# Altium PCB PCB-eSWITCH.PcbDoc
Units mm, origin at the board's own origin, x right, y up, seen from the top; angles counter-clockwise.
Board outline 50 x 34 mm, 4 copper layers (Top Layer 1, Inner1, Inner2, Bottom Layer 1), stack 1.57 mm thick; 56 components, 38 nets, 225 pads, 153 vias.
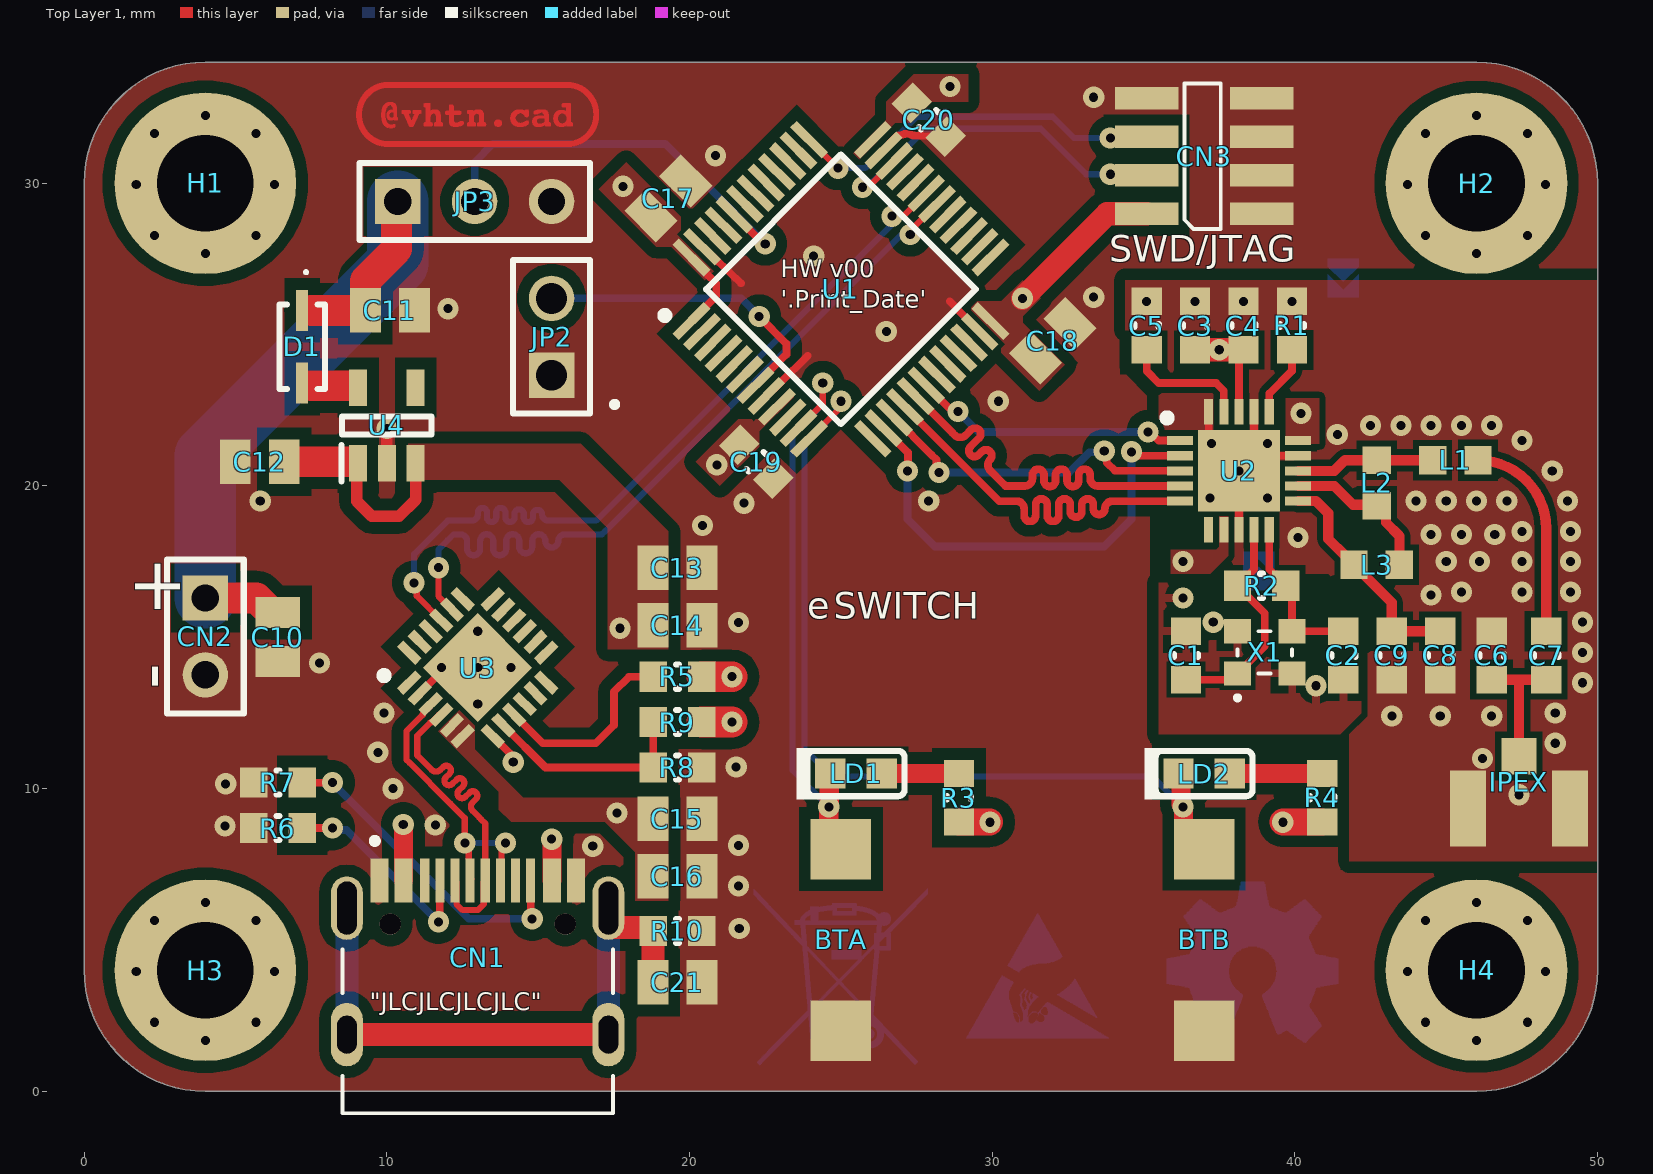
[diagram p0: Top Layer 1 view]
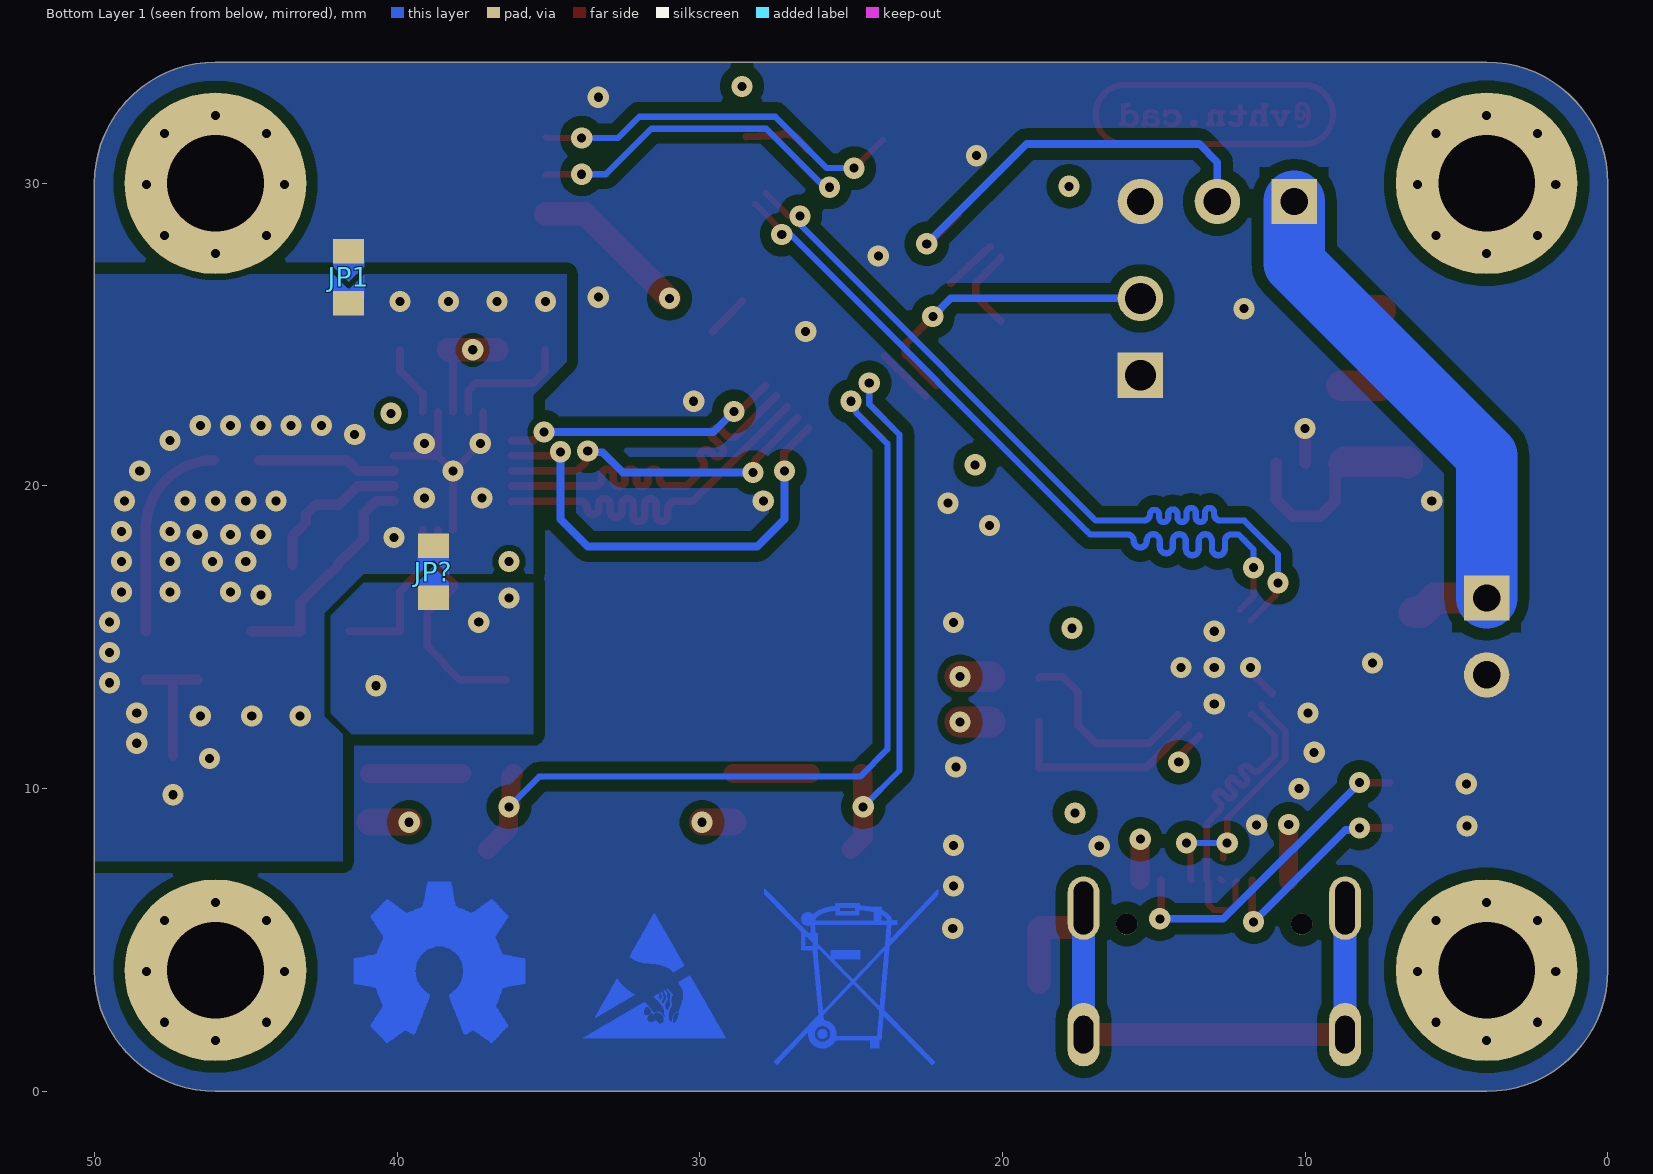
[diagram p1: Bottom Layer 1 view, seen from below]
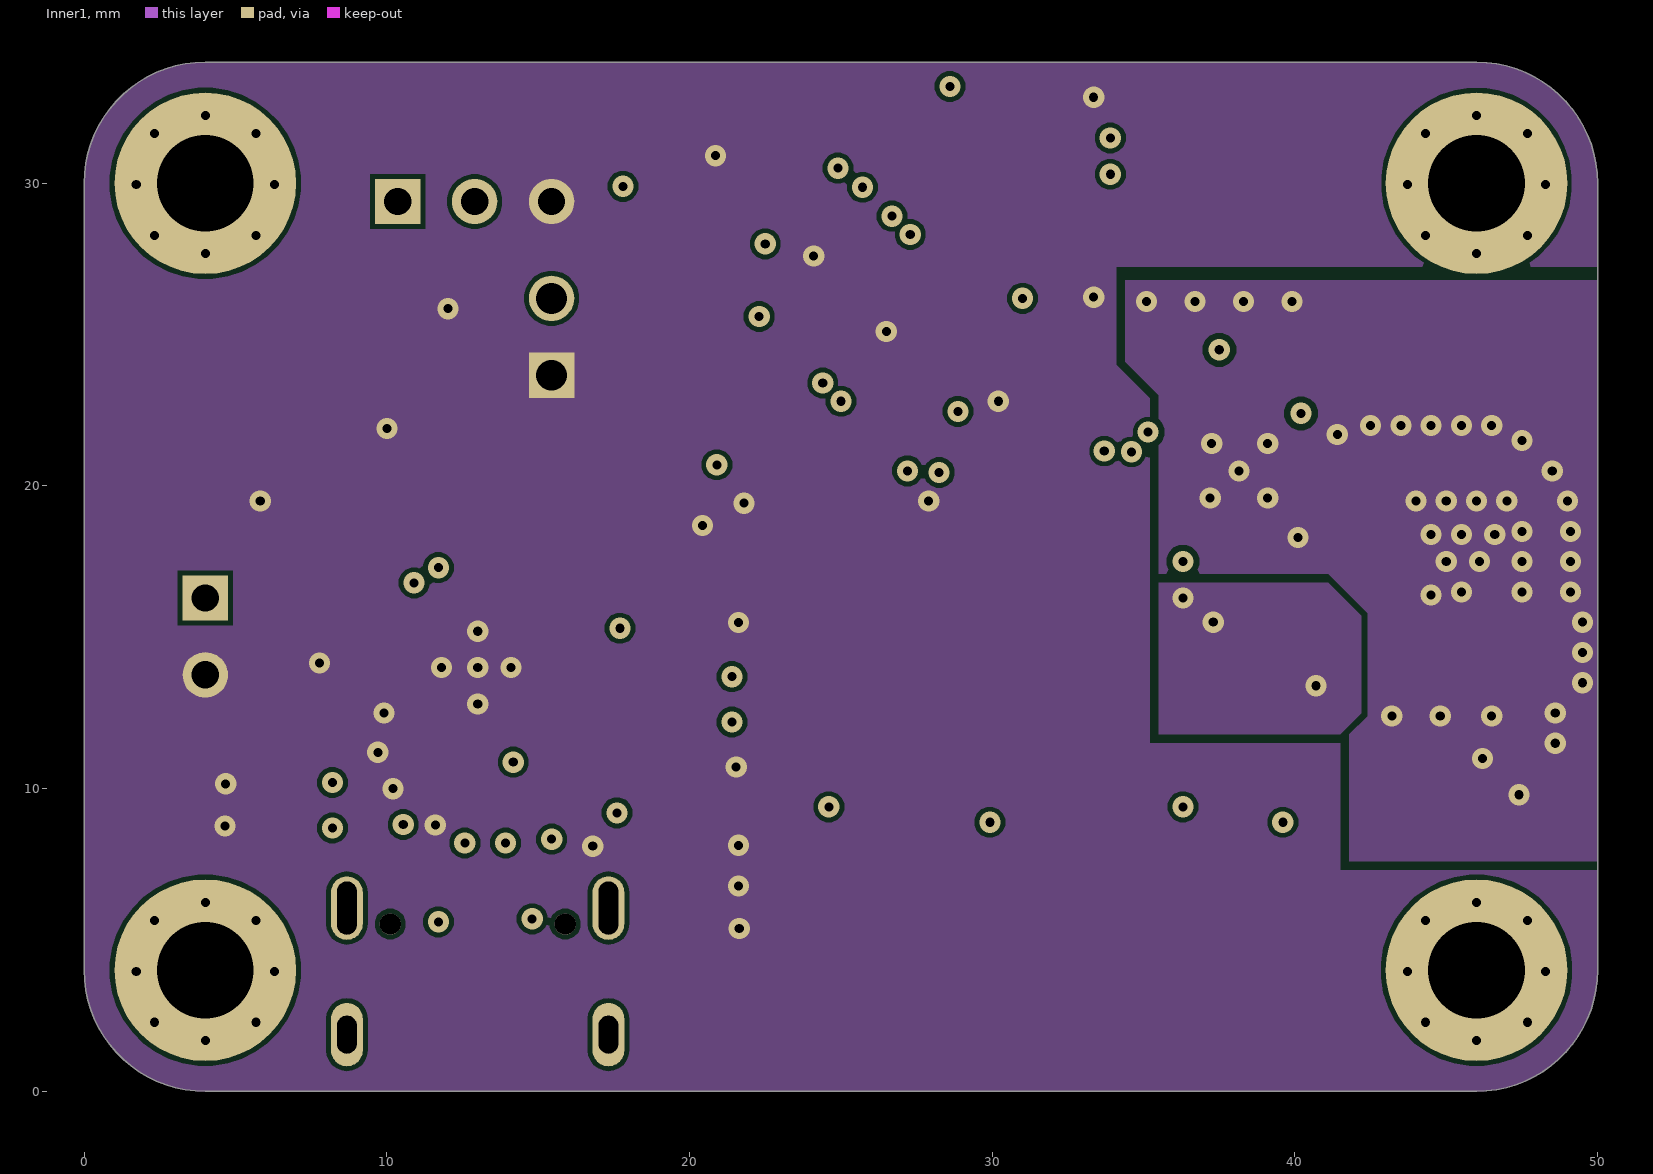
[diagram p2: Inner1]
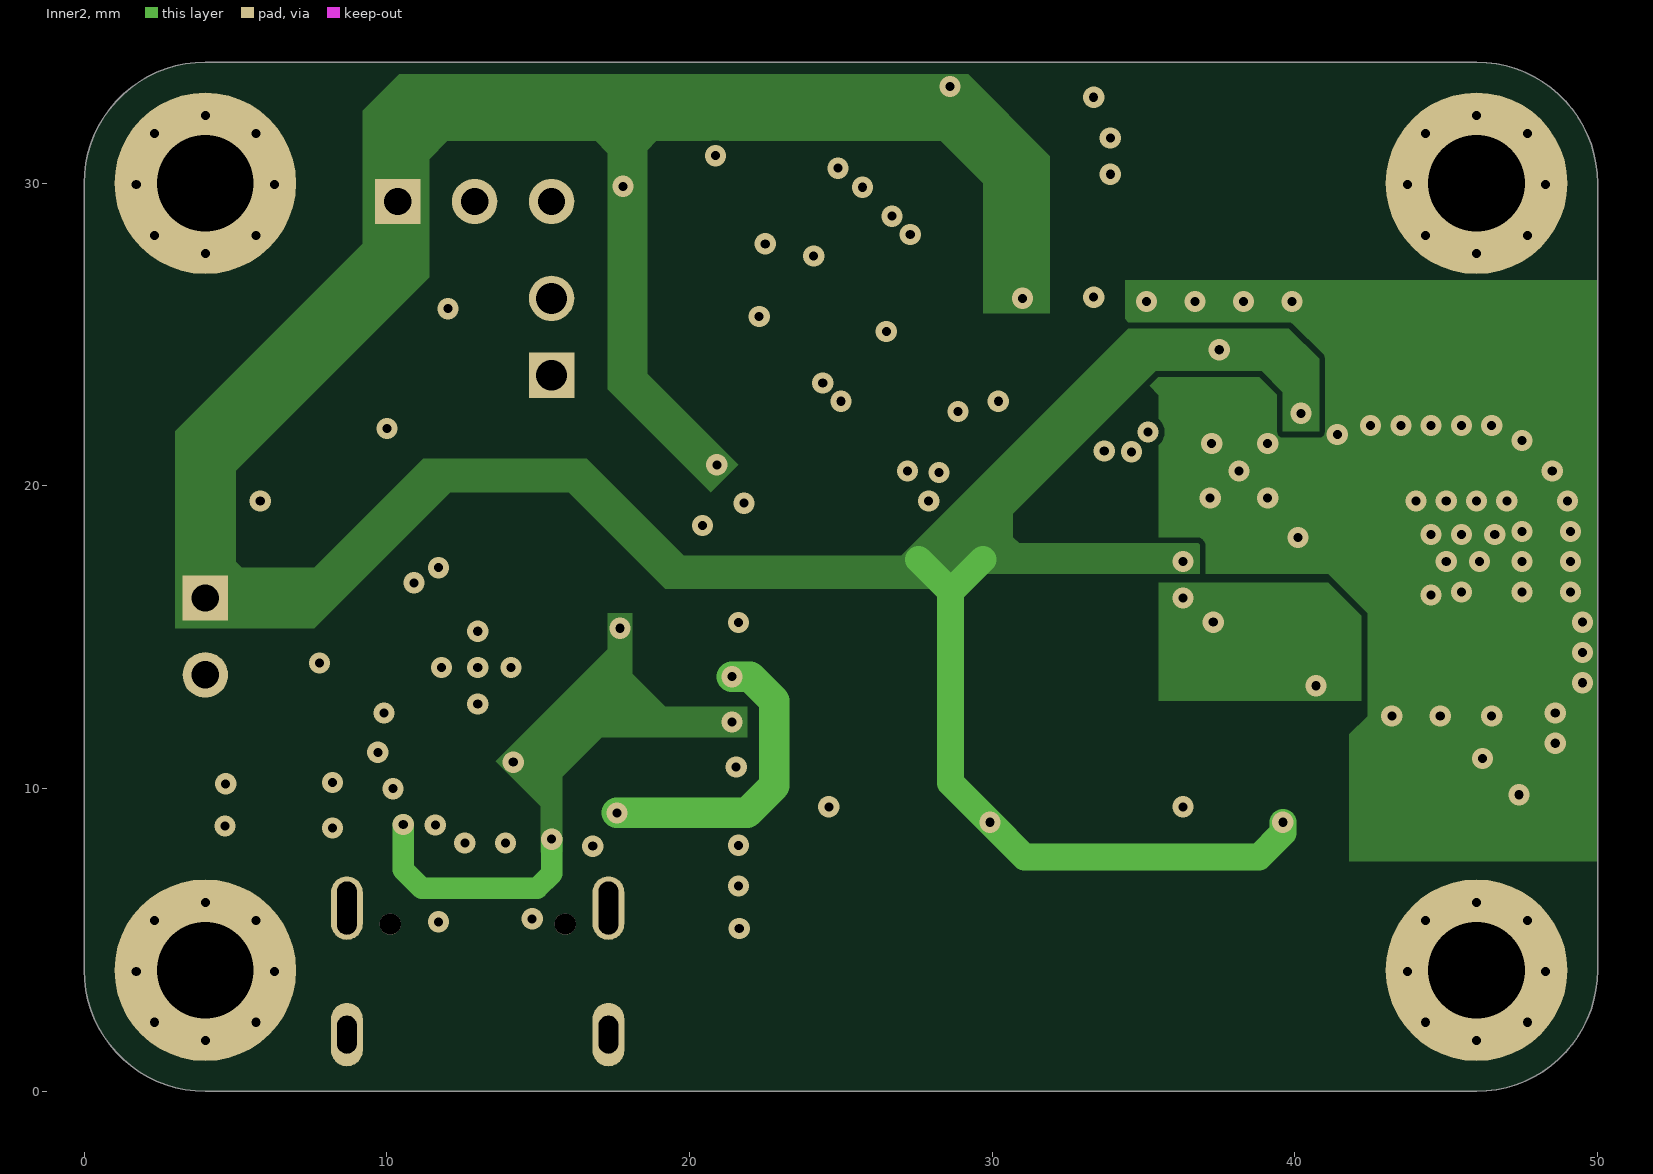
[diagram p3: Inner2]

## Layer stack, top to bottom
Top Solder: solder mask 0.0102, Solder Resist, Dk 3.5
Top Layer 1: signal copper 0.035
Dielectric 2: prepreg 0.2, PP-006, Dk 4.6
Inner1: signal copper 0.0175
Dielectric 1: dielectric 1.065, FR-4, Dk 4.6
Inner2: signal copper 0.0175
Dielectric 3: prepreg 0.2, PP-006, Dk 4.6
Bottom Layer 1: signal copper 0.035
Bottom Solder: solder mask 0.0102, Solder Resist, Dk 3.5

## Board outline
0,4 0,30 cw(c4,30) 4,34 46,34 cw(c46,30) 50,30 50,4 cw(c46,4) 46,0 4,0 cw(c4,4)

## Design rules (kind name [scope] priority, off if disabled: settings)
Clearance Clearance_2 [InNamedPolygon('GND1')] p1: gap=0.152 ignorepadtopadclearanceinfootprint=FALSE
Clearance Clearance_3 [InNamedPolygon('GND')] p2: gap=0.381 ignorepadtopadclearanceinfootprint=FALSE
Clearance Clearance_1 [InNamedPolygon('AGND')] p3: gap=0.203 ignorepadtopadclearanceinfootprint=FALSE
Clearance [All] p4: gap=0.152 ignorepadtopadclearanceinfootprint=FALSE
DiffPairsRouting [All] p1: maxlimit=0.254 minlimit=0.152 mostfreqgap=0.152 toplayer_minwidth=0.152 toplayer_maxwidth=0.381 toplayer_prefwidth=0.229 midlayer1_minwidth=0.152 midlayer1_maxwidth=0.381 midlayer1_prefwidth=0.229 midlayer2_minwidth=0.152 midlayer2_maxwidth=0.381 midlayer2_prefwidth=0.229 bottomlayer_minwidth=0.152 bottomlayer_maxwidth=0.381 bottomlayer_prefwidth=0.229 maxuncoupledlength=12.7
HoleSize [All] p1: absolutevalues=TRUE maxlimit=4 minlimit=0.025 maxpercent=80.000 minpercent=20.000
MinimumSolderMaskSliver [All] p1: minsoldermaskwidth=0.025
PolygonConnect PolygonConnect_6 [All vs IsNamedPolygon('5V')] p1: connectstyle=Direct reliefconductorwidth=0.254 reliefentries=4 polygonreliefangle="90 Angle" airgapwidth=0.254
PolygonConnect PolygonConnect_5 [All vs IsNamedPolygon('3v3P')] p2: connectstyle=Direct reliefconductorwidth=0.254 reliefentries=4 polygonreliefangle="90 Angle" airgapwidth=0.254
PolygonConnect PolygonConnect_4 [All vs IsNamedPolygon('3v3')] p3: connectstyle=Direct reliefconductorwidth=0.254 reliefentries=4 polygonreliefangle="90 Angle" airgapwidth=0.254
PolygonConnect PolygonConnect_3 [All vs IsNamedPolygon('GND1')] p4: connectstyle=Direct reliefconductorwidth=0.254 reliefentries=4 polygonreliefangle="90 Angle" airgapwidth=0.254
PolygonConnect PolygonConnect_2 [All vs IsNamedPolygon('AGND')] p5: connectstyle=Direct reliefconductorwidth=0.254 reliefentries=4 polygonreliefangle="90 Angle" airgapwidth=0.254
PolygonConnect PolygonConnect_1 [All vs IsNamedPolygon('GND')] p6: connectstyle=Direct reliefconductorwidth=0.254 reliefentries=4 polygonreliefangle="90 Angle" airgapwidth=0.254
PolygonConnect PolygonConnect_7 [All vs IsNamedPolygon('XTGND')] p7: connectstyle=Direct reliefconductorwidth=0.254 reliefentries=4 polygonreliefangle="90 Angle" airgapwidth=0.254
PolygonConnect [All] p8: connectstyle=Relief reliefconductorwidth=0.254 reliefentries=4 polygonreliefangle="90 Angle" airgapwidth=0.254
RoutingVias [All] p1: holewidth=0.3 width=0.7 viastyle="Through Hole" minholewidth=0.3 minwidth=0.7 maxholewidth=0.711 maxwidth=1.27
SilkToSilkClearance [All] p1: silktosilkclearance=0
SilkToSolderMaskClearance [IsPad] p1: minsilkscreentomaskgap=0.076 clearancetoexposedcopper=TRUE
SolderMaskExpansion [All] p1: expansion=0.102 istentingtop=FALSE
Width [All] p1: maxlimit=2.54 minlimit=0.152 preferedwidth=0.381
25 further rules are at their usual default settings.

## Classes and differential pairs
differential pair USBD: +USBD_P -USBD_N

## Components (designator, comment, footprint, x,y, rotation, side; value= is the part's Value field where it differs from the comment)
BTA "SWITCH" SKPMAME010 25,5 r90 top
BTB "SWITCH" SKPMAME010 37,5 r90 top
C1 "22pF" 0603C 36.4,14.4 r90 top
C2 "22pF" 0603C 41.6,14.4 r270 top
C3 "10nF" 0603C 36.7,25.3 r90 top
C4 "1nF" 0603C 38.3,25.3 r90 top
C5 "33nF" 0603C 35.1,25.3 r90 top
C6 "1pF" 0603C 46.5,14.4 r90 top
C7 "1.5pF" 0603C 48.3,14.4 r270 top
C8 "4.7pF" 0603C 44.8,14.4 r90 top
C9 "2.2nF" 0603C 43.2,14.4 r90 top
C10 "10uF" CAPC2012X94N 6.4,15.01 r270 top
C11 "1uF" CAPC2012X94N 10.1,25.8 r0 top
C12 "1uF" CAPC2012X94N 5.8,20.8 r180 top
C13 "100nF" CAPC2012X94N 19.6,17.3 r0 top
C14 "4.7uF" CAPC2012X94N 19.6,15.4 r0 top
C15 "100nF" CAPC2012X94N 19.6,9 r0 top
C16 "4.7uF" CAPC2012X94N 19.6,7.1 r0 top
C17 "1uF" CAPC2012X94N 19.3,29.5 r45 top
C18 "1uF" CAPC2012X94N 32,24.8 r45 top
C19 "100nF" 0603C 22.2,20.8 r135 top
C20 "100nF" 0603C 27.9,32.1 r135 top
C21 "100nF" CAPC2012X94N 19.6,3.6 r0 top
CN1 "USB-C" "USB TYPE C" 13,2.975 r0 top locked
CN2 "ER26500" HDR1X2 4,16.3 r270 top
CN3 "JTAG/SWD" "MINI PIN HEADER 2X4" 37,30.9 r90 top
D1 "BAT60JFILM" SOD-323 7.2,24.6 r90 top
H1 "" "MOUNTING HOLE" 4,30 r0 top
H2 "" "MOUNTING HOLE" 46,30 r0 top
H3 "" "MOUNTING HOLE" 4,4 r0 top
H4 "" "MOUNTING HOLE" 46,4 r0 top
IPEX "SMA" IPEX 47.5,9.4 r180 top
JP1 "CLOSED" SB_0603 41.6,26.9 r90 bottom
JP2 "JP2" HDR_1x2_2R54_V_M_S 15.44,23.66 r90 top
JP3 "Header 3" HDR1X3 10.36,29.4 r0 top
JP? "CLOSED" SB_0603 38.8,17.166 r270 bottom
L1 "3.9nH" RESC1608X55N 45.3,20.85 r0 top value=10mH
L2 "8.2nH" RESC1608X55N 42.7,20.1 r90 top value=10mH
L3 "2.7nH" RESC1608X55N 42.7,17.4 r0 top value=10mH
LD1 "Red" 0603D-R 25.5,10.5 r0 top
LD2 "Red" 0603D-R 37,10.5 r0 top
R1 "22K" 0603R 39.9,25.3 r90 top
R2 "1M" 0603R 38.9,16.7 r180 top
R3 "1K" 0603R 28.9,9.7 r270 top
R4 "1K" 0603R 40.9,9.7 r270 top
R5 "1K" 0603R 19.6,13.7 r180 top
R6 "4K7" 0603R 6.4,8.7 r0 top
R7 "4K7" 0603R 6.4,10.2 r0 top
R8 "47K" 0603R 19.6,10.7 r0 top
R9 "22K" 0603R 19.6,12.2 r180 top
R10 "1M" 0603R 19.6,5.3 r180 top
U1 "STM32F103C8T6TR" QFP50P900X900X160-48N 25,26.5 r45 top
U2 "NRF24L01" QFN50P400X400X95-21N-D 38.15,20.5 r0 top
U3 "CP2102N" QFN50P400X400X80-25N-D 13,14 r45 top
U4 "AP2112K-3.3TRG1" SOT95P282X130-5N 10,22 r90 top
X1 "16MHz" XTAL_SMD 39,14.5 r0 top

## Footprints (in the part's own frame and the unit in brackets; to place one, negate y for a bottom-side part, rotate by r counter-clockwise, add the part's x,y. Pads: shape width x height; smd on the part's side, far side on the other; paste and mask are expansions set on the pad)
0603C [mm] "Chip Capacitor, Body 1.6x0.8mm, Height 1.0mm, IPC Medium Density"
  rect 0.9x1 smd: 1(-0.8,0) 2(0.8,0)
  silkscreen extent -0.05,-0.4 0.05,0.4, body extent -0.87,-0.48 0.88,0.47, height 1
0603D-R [mm] "LED, SMT, Body 1.6 x 0.8 mm, 0.25mm Thickness"
  rect 1x1 smd paste+0 mask+0: 1(0.85,0) 2(-0.85,0)
  silkscreen extent -1.98,-0.86 1.6,0.84, body extent -0.8,-0.4 0.8,0.4, height 0.25
0603R [mm] "Chip Resistor, Body 1.6x0.8mm, IPC Medium Density"
  rect 0.9x1 smd: 1(-0.8,0) 2(0.8,0)
  silkscreen extent -0.05,-0.4 0.05,0.4, body extent -0.85,-0.47 0.85,0.47, height 0.6
CAPC2012X94N [mm]
  rect 1.02x1.47 smd: 1(-0.81,0) 2(0.81,0)
  body extent -1,-0.63 1,0.63, height 0.94
HDR1X2 [mm] "Connector; Header; 2 Position"
  rect 1.5x1.5 hole 0.9: 1(0,0)
  round 1.5 hole 0.9: 2(2.54,0)
  silkscreen extent -1.27,-1.27 3.81,1.27
HDR1X3 [mm] "Connector; Header; 3 Position"
  rect 1.5x1.5 hole 0.9: 1(0,0)
  round 1.5 hole 0.9: 2(2.54,0) 3(5.08,0)
  silkscreen extent -1.27,-1.27 6.35,1.27
HDR_1x2_2R54_V_M_S [mm] "Male Header, Pitch 2.54mm, 4x1 Position, Mated Height 6mm, Tail Length 3mm"
  rect 1.5x1.5 hole 1.02: 1(0,0)
  round 1.5 hole 1.02: 2(2.54,0)
  silkscreen extent -1.27,-2.14 3.81,1.27, body extent -1.27,-1.27 3.81,1.27, height 9
IPEX [mm]
  rect 1.2x2.5 smd: 1(-1.585,0.055) 2(1.785,0.055)
  rect 1.15x1.2 smd: 3(0.1,-1.675)
  body extent -1.5,-1.5 1.5,1.6
"MINI PIN HEADER 2X4" [mm]
  rect 0.74x2.1 smd mask+0.01: 1(-1.905,1.9) 2(-1.905,-1.9) 3(-0.635,1.9) 4(-0.635,-1.9) 5(0.635,1.9) 6(0.635,-1.9) 7(1.905,1.9) 8(1.905,-1.9)
  silkscreen extent -2.4,-0.55 2.39,0.65, body extent -2.55,-2.81 2.53,2.76, height 4.4
"MOUNTING HOLE" [mm]
  round 6 hole 3.2 unplated mask+0.05: 1(0,0)
QFN50P400X400X80-25N-D [mm]
  rect 0.85x0.3 smd mask+0.051: 1(-1.95,1.25) 2(-1.95,0.75) 3(-1.95,0.25) 4(-1.95,-0.25) 5(-1.95,-0.75) 6(-1.95,-1.25) 13(1.95,-1.25) 14(1.95,-0.75) 15(1.95,-0.25) 16(1.95,0.25) 17(1.95,0.75) 18(1.95,1.25)
  rect 0.3x0.85 smd mask+0.051: 7(-1.25,-1.95) 8(-0.75,-1.95) 9(-0.25,-1.95) 10(0.25,-1.95) 11(0.75,-1.95) 12(1.25,-1.95) 19(1.25,1.95) 20(0.75,1.95) 21(0.25,1.95) 22(-0.25,1.95) 23(-0.75,1.95) 24(-1.25,1.95)
  rect 2.55x2.55 smd mask+0.051: 25(0,0)
  silkscreen extent -2.5,1.88 -2.25,2.12, body extent -2.05,-2.05 2.05,2.05, height 0.8
QFN50P400X400X95-21N-D [mm]
  rect 0.85x0.3 smd mask+0.05: 1(-1.95,1) 2(-1.95,0.5) 3(-1.95,0) 4(-1.95,-0.5) 5(-1.95,-1) 11(1.95,-1) 12(1.95,-0.5) 13(1.95,0) 14(1.95,0.5) 15(1.95,1)
  rect 0.3x0.85 smd mask+0.05: 6(-1,-1.95) 7(-0.5,-1.95) 8(0,-1.95) 9(0.5,-1.95) 10(1,-1.95) 16(1,1.95) 17(0.5,1.95) 18(0,1.95) 19(-0.5,1.95) 20(-1,1.95)
  rect 2.7x2.7 smd mask+0.05: 21(0,0)
  silkscreen extent -2.5,1.63 -2.25,1.87, body extent -2.05,-2.05 2.05,2.05, height 0.95
QFP50P900X900X160-48N [mm]
  rect 1.475x0.3 smd mask+0.051: 1(-4.238,2.75) 2(-4.238,2.25) 3(-4.238,1.75) 4(-4.238,1.25) 5(-4.238,0.75) 6(-4.238,0.25) 7(-4.238,-0.25) 8(-4.238,-0.75) 9(-4.238,-1.25) 10(-4.238,-1.75) 11(-4.238,-2.25) 12(-4.238,-2.75) 25(4.238,-2.75) 26(4.238,-2.25) 27(4.238,-1.75) 28(4.238,-1.25) 29(4.238,-0.75) 30(4.238,-0.25) 31(4.238,0.25) 32(4.238,0.75) 33(4.238,1.25) 34(4.238,1.75) 35(4.238,2.25) 36(4.238,2.75)
  rect 0.3x1.475 smd mask+0.051: 13(-2.75,-4.238) 14(-2.25,-4.238) 15(-1.75,-4.238) 16(-1.25,-4.238) 17(-0.75,-4.238) 18(-0.25,-4.238) 19(0.25,-4.238) 20(0.75,-4.238) 21(1.25,-4.238) 22(1.75,-4.238) 23(2.25,-4.238) 24(2.75,-4.238) 37(2.75,4.238) 38(2.25,4.238) 39(1.75,4.238) 40(1.25,4.238) 41(0.75,4.238) 42(0.25,4.238) 43(-0.25,4.238) 44(-0.75,4.238) 45(-1.25,4.238) 46(-1.75,4.238) 47(-2.25,4.238) 48(-2.75,4.238)
  silkscreen extent -4.85,-3.15 3.15,3.62, body extent -4.5,-4.5 4.5,4.5, height 1.6
RESC1608X55N [mm]
  rect 0.9x0.95 smd: 1(-0.75,0) 2(0.75,0)
  body extent -0.77,-0.4 0.77,0.4, height 0.55
SB_0603 [mil] "Jumper"
  rect 32x40 smd mask+2: 1(33.75,0) 2(-33.75,0)
  Top Layer 1 region: 23.75,20 13.75,20 -6.25,0 13.75,-20 23.75,-20
  Top Layer 1 region: -26.25,0 -16.25,0 3.75,20 -26.25,20
  Top Layer 1 region: -26.25,0 -16.25,0 3.75,-20 -26.25,-20
SKPMAME010 [mm]
  rect 2x2 smd: 1(-3,0) 2(3,0)
  body extent -3.3,-2.97 3.3,2.97, height 5
SOD-323 [mm] "Diode"
  rect 1.35x0.4 smd: 1(-1.2,0) 2(1.2,0)
  silkscreen extent -1.4,-0.75 2.51,0.75, body extent -1.35,-0.72 1.35,0.72, height 1.17
SOT95P282X130-5N [mm]
  rect 1.2x0.6 smd: 1(-1.25,0.95) 2(-1.25,0) 3(-1.25,-0.95) 4(1.25,-0.95) 5(1.25,0.95)
  silkscreen extent -1.85,-1.48 0.3,1.5, body extent -1.41,-1.48 1.41,1.48, height 1.3
"USB TYPE C" [mm]
  rect 0.6x1.45 smd mask+0.05: A1B12(-3.25,3.995) A4B9(-2.45,3.995) B1A12(3.25,3.995) B4A9(2.45,3.995)
  rect 0.3x1.45 smd mask+0.05: A5(-1.25,3.995) A6(-0.25,3.995) A7(0.25,3.995) A8(1.25,3.995) B5(1.75,3.995) B6(0.75,3.995) B7(-0.75,3.995) B8(-1.75,3.995)
  oval 1.05x2.1 hole 0.65 slot 1.75 at 90 deg mask+0.05: S1(-4.32,3.08) S2(4.32,3.08)
  oval 1.05x2.1 hole 0.65 slot 1.25 at 90 deg mask+0.05: S3(-4.32,-1.1) S4(4.32,-1.1)
  round 0.7 hole 0.7 unplated: ""(-2.89,2.55) ""(2.89,2.55)
  silkscreen extent -4.47,-3.7 4.47,5.4, body extent -4.47,-3.75 4.47,4.15, height 3.16
XTAL_SMD [mm]
  rect 0.9x0.8 smd: 1(-0.9,-0.7) 2(0.9,-0.7) 3(0.9,0.7) 4(-0.9,0.7)
  silkscreen extent -0.95,-1.55 0.9,0.7, body extent -1.65,-1.3 1.65,1.3, height 1.1

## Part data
C1 C2 C3 C4 C5 C6 C7 C8 C9 C10 C11 C12 C13 C14 C15 C16 C17 C18 C19 C20 C21: library part CAP, "Capacitor"
CN2: library part "Header 2", "Header, 2-Pin"
CN3: library part "Header 4X2", "Header, 4-Pin, Dual row"
D1: Manuf_1=STM
H1 H2 H3 H4: library part TP
JP1 JP?: library part "Circuit Breaker", "Circuit Breaker"
JP3: "Header, 3-Pin"
L1 L2 L3: library part Inductor, "Inductor"
LD1 LD2: library part LED2, "Typical RED, GREEN, YELLOW, AMBER GaAs LED"
R1 R2 R3 R4 R5 R6 R7 R8 R9 R10: library part RESISTOR
U1: "Integrated Circuit", Manufacturer_Name=STMicroelectronics, Mouser Part Number=511-STM32F103C8T6TR
U2: "Integrated Circuit", Manufacturer_Name="Nordic Semiconductor", Mouser Part Number=949-NRF24L01
U4: "Integrated Circuit", Manufacturer_Name="Diodes Inc.", Mouser Part Number=621-AP2112K-3.3TRG1
X1: library part XTAL_5032, "Crystal Oscillator"

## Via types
v1: diameter 0.7, hole 0.3, Top Layer 1 to Bottom Layer 1, tented both sides, 153 vias

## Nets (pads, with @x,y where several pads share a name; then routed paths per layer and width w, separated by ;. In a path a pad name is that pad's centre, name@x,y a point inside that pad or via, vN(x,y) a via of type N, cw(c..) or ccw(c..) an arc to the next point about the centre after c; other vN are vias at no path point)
3V3: C3.1 C4.1 C10.1 C11.1 C17.1 C18.1 C19.2 C20.2 CN2.1 CN3.1 D1.2 JP3.1 R3.2 R4.2 U1.1 U1.9 U1.24 U1.36 U1.48 U2.7 U2.15 U2.18 | length 60.5
  Top Layer 1 w0.152: D1.2 7.5,25.8
  Top Layer 1 w0.254: U1.1 20.879,26.268 20.879,26.695 20.559,27.015 20.559,27.019 20.059,27.52 U1.48 ; U2.18 38.15,24.35 C4.1
  Top Layer 1 w0.762: v1(31,26.2) 33.795,28.995 CN3.1 ; C3.1 C4.1
  Top Layer 1 w0.889: R3.2 28.906,8.894 v1@29.917,8.894 ; v1@39.609,8.9 R4.2
  Top Layer 1 w1.016: CN2.1 5.695,16.3 6.175,15.82 C10.1 ; 7.5,25.8 C11.1 9.292,25.802 9.292,26.792 10.318,27.818 10.318,29.358 JP3.1
  Inner2 w0.889: 27.559,17.577 28.626,16.51 ; 29.693,17.577 28.626,16.51 ; v1(39.599,8.89) 39.599,8.534 38.811,7.747 31.064,7.747 v1(29.921,8.89) 28.626,10.185 28.626,16.51
  Bottom Layer 1 w2.032: CN2.1 4,21 10.36,27.36 JP3.1
  other v1: 36.3,17.5 20.9,20.7 40.2,22.4 37.5,24.5 17.8,29.9 28.6,33.2
3V3P: C15.1 C16.1 R5.1 U3.5 U3.6 | length 11.1
  Top Layer 1 w1.016: R5.1 v1(21.4,13.7)
  Inner2 w1.016: v1(17.6,9.2) 21.9,9.2 22.8,10.1 22.8,12.9 22,13.7 v1(21.4,13.7)
+5: C12.1 C13.1 C14.1 CN1.A4B9 CN1.B4A9 R9.1 U3.7 U4.1 U4.3 | length 20.7
  Top Layer 1 w0.152: 8.7,20.8 9,20.8 U4.1
  Top Layer 1 w0.254: U3.7 14.089,11.143 14.089,10.96 v1(14.175,10.875)
  Top Layer 1 w0.381: U4.1 9,20.7 9,19.5 9.5,19 10.4,19 10.95,19.55 U4.3
  Top Layer 1 w0.635: v1(10.541,8.814) 10.55,8.805 CN1.A4B9 ; v1(15.443,8.331) 15.45,8.324 CN1.B4A9
  Top Layer 1 w1.016: C12.1@6.612,20.75 6.61,20.752 C12.1 8.7,20.8 ; R9.1 v1(21.4,12.2)
  Inner2 w0.711: v1(10.541,8.814) 10.541,7.315 11.151,6.706 14.961,6.706 15.443,7.188 v1(15.443,8.331)
  other v1: 17.7,15.3
AGND: C3.2 C4.2 C5.2 C6.2 C8.1 C9.1 IPEX.1 IPEX.2 JP1.2 JP?.2 R1.2 U2.8 U2.14 U2.17 U2.20 U2.21 | length 7.9
  Top Layer 1 w0.254: U2.20 37.15,21.5 v1(38.15,20.5) ; U2.8 v1(38.15,20.5) ; U2.17 U2.21@38.65,21 ; U2.14 U2.21@38.65,21 ; v1(38.15,20.5) U2.21@38.65,21
  other v1: 47.4,9.8 46.2,11 48.6,11.5 43.2,12.4 44.8,12.4 46.5,12.4 48.6,12.5 49.5,13.5 49.5,14.5 49.5,15.5 44.5,16.4 45.5,16.5 47.5,16.5 49.1,16.5 45,17.5 46.1,17.5 47.5,17.5 49.1,17.5 40.1,18.3 44.5,18.4 45.5,18.4 46.6,18.4 47.5,18.5 49.1,18.5 44,19.5 45,19.5 46,19.5 47,19.5 49,19.5 37.2,19.6 39.1,19.6 48.5,20.5 37.25,21.4 39.1,21.4 47.5,21.5 41.4,21.7 42.5,22 43.5,22 44.5,22 45.5,22 46.5,22 35.1,26.1 36.7,26.1 38.3,26.1 39.9,26.1
Button_A: BTA.2 LD1.2 U1.11 | length 19.4
  Top Layer 1 w0.203: U1.11 24.4,22.718 v1(24.4,23.4)
  Top Layer 1 w0.635: LD1.2 24.613,10.464 24.613,9.431 24.6,9.418 v1(24.6,9.4) 24.6,8.4 BTA.2
  Bottom Layer 1 w0.203: v1(24.4,23.4) 24.4,22.7 23.4,21.7 23.4,10.6 v1(24.6,9.4)
Button_B: BTB.2 LD2.2 U1.12 | length 29.5
  Top Layer 1 w0.203: U1.12 v1@24.909,22.52
  Top Layer 1 w0.635: LD2.2 36.236,10.413 36.236,9.481 36.3,9.418 v1(36.3,9.4) 36.3,9.382 36.317,9.365 36.317,8.682 BTB.2
  Bottom Layer 1 w0.203: v1(25.004,22.799) 25.004,22.664 24.841,22.502 24.841,22.441 23.8,21.4 23.8,11.3 24.7,10.4 35.3,10.4 v1(36.3,9.4)
CE: U1.18 U2.1 | length 9.1
  Top Layer 1 w0.254: U1.18 28.596,22.55 28.779,22.55 v1(28.865,22.465) ; v1(35.15,21.781) 35.224,21.781 35.505,21.5 U2.1
  Bottom Layer 1 w0.254: v1(28.865,22.465) 29.549,21.781 v1(35.15,21.781)
CSN: U1.14 U2.2 | length 15.1
  Top Layer 1 w0.254: U1.14 27.215,21.103 27.215,20.515 v1(27.2,20.5) ; v1@34.85,21 U2.2
  Bottom Layer 1 w0.254: v1(27.2,20.5) 27.2,18.9 28.1,18 33.7,18 34.6,18.9 v1(34.6,21.129)
GND: BTA.1 BTB.1 C10.2 C11.2 C12.2 C13.2 C14.2 C15.2 C16.2 C17.2 C18.2 C19.1 C20.1 C21.2 CN1.A1B12 CN1.B1A12 CN2.2 CN3.2 CN3.4 CN3.6 CN3.7 CN3.8 JP1.1 JP2.1 JP3.3 R6.1 R7.1 R8.2 R10.1 U1.8 U1.23 U1.35 U1.47 U3.2 U3.25 U4.2 | length 9.7
  Top Layer 1 w0.254: U3.2 11.8,13.861 v1(11.8,14) ; U1.47 20.858,27.488 21.7,26.7 ; U1.8 22.972,23.398 23.9,24.3 ; U1.35 26.798,31.498 26.821,31.521 26.829,31.528 26.836,31.535 cw(c27.001,31.342) 26.953,31.591 27.011,31.602 ccw(c26.964,31.852) 27.063,31.618 cw(c27.175,31.362) 27.307,31.608 ccw(c27.426,31.832) 27.414,31.578 28.027,31.553 C20.1 ; 28.6,26.1 29.158,25.532 29.16,25.53 U1.23
  Top Layer 1 w0.381: U4.2 v1(10,21.9)
  other v1: 21.641,5.385 21.615,6.782 16.8,8.1 21.615,8.128 4.648,8.763 11.6,8.8 10.2,10 4.674,10.16 21.539,10.719 9.7,11.2 9.9,12.5 13,12.8 13,14 14.1,14 7.772,14.148 13,15.2 21.615,15.494 20.422,18.694 21.793,19.431 5.817,19.507 27.9,19.5 30.2,22.8 26.5,25.1 12.014,25.857 33.35,26.238 24.1,27.6 20.853,30.912 33.35,32.842
MISO: U1.16 U2.5 | length 14.1
  Top Layer 1 w0.254: U1.16 30.232,19.5 30.291,19.5 30.799,19.5 cw(c30.799,19.246) 31.053,19.246 31.053,19.02 ccw(c31.243,19.02) 31.434,19.02 31.434,19.385 cw(c31.624,19.385) 31.815,19.385 31.815,19.02 ccw(c32.005,19.02) 32.196,19.02 32.196,19.385 cw(c32.386,19.385) 32.577,19.385 32.577,19.159 ccw(c32.767,19.159) 32.958,19.159 32.958,19.385 cw(c33.148,19.385) 33.339,19.385 33.339,19.246 ccw(c33.529,19.246) 33.72,19.246 cw(c33.974,19.246) 33.974,19.5 34.506,19.5 U2.5
MOSI: U1.17 U2.4 | length 14.1
  Top Layer 1 w0.254: U1.17 28.671,21.769 28.76,21.679 ccw(c28.94,21.858) 29.12,21.679 29.297,21.856 cw(c29.432,21.722) 29.567,21.856 cw(c29.432,21.722) 29.567,21.587 29.278,21.298 ccw(c29.413,21.164) 29.278,21.029 ccw(c29.413,21.164) 29.547,21.029 29.659,21.14 cw(c29.793,21.005) 29.928,21.14 cw(c29.793,21.005) 29.928,20.871 ccw(c30.107,20.691) 29.928,20.511 30.334,20.105 30.424,20.015 30.439,20 30.947,20 31.074,20 ccw(c31.074,20.254) 31.328,20.254 31.328,20.366 cw(c31.519,20.366) 31.709,20.366 31.709,20.172 ccw(c31.9,20.172) 32.09,20.172 32.09,20.366 cw(c32.281,20.366) 32.471,20.366 32.471,20.172 ccw(c32.662,20.172) 32.852,20.172 32.852,20.366 cw(c33.043,20.366) 33.233,20.366 33.233,20.254 ccw(c33.487,20.254) 33.487,20 33.952,20 U2.4
NetC1_1: C1.1 R2.2 U2.9 X1.1 | length 7.6
  Top Layer 1 w0.254: C1.1 37.95,13.6 38.423,14.073 38.423,14.123 39,14.7 39,15.8 38.473,16.327 38.423,16.327 38.1,16.65 R2.2 38.1,16.75 38.423,17.073 38.473,17.073 38.65,17.25 U2.9
NetC2_1: C2.1 R2.1 U2.10 X1.3 | length 5.4
  Top Layer 1 w0.254: U2.10 39.15,17.25 39.327,17.073 39.377,17.073 39.7,16.75 R2.1 39.9,16.5 X1.3 C2.1
NetC5_1: C5.1 U2.19 | length 4.2
  Top Layer 1 w0.254: C5.1 35.1,23.8 35.5,23.4 37.4,23.4 37.65,23.15 U2.19
NetC6_1: C6.1 C7.2 IPEX.3 | length 4.3
  Top Layer 1 w0.337: C6.1@46.6,13.6 47.45,13.6 ; IPEX.3 47.4,13.55 cw(c47.45,13.55) 47.45,13.6 ; C7.2 47.45,13.6
NetC7_1: C7.1 L1.2 | length 6.9
  Top Layer 1 w0.337: L1.2 cw(c46.05,18.6) 48.3,18.6 C7.1
NetC8_2: C8.2 C9.2 L3.1 U2.11 | length 7.6
  Top Layer 1 w0.337: U2.11 40.7,19.5 41.1,19.1 41.1,18.25 41.643,17.707 41.668,17.707 41.95,17.425 L3.1 41.95,17.375 42.232,17.093 42.257,17.093 43.2,16.15 C9.2 ; C9.2 C8.2
NetC21_1: C21.1 CN1.S1 CN1.S2 CN1.S3 CN1.S4 R10.2 | length 20.8
  Top Layer 1 w0.762: CN1.S3 CN1.S4 ; CN1.S2 17.32,5.608 17.509,5.419 18.731,5.419 18.8,5.35 R10.2 18.795,5.295 18.795,3.605 C21.1
  Bottom Layer 1 w0.762: CN1.S3 CN1.S1 ; CN1.S4 CN1.S2
NetCN1_A5: CN1.A5 R6.2 | length 7.2
  Top Layer 1 w0.254: R6.2 v1(8.2,8.7) ; v1(11.7,5.6) 11.75,5.65 CN1.A5
  Bottom Layer 1 w0.254: v1(8.2,8.7) 8.263,8.637 8.663,8.637 v1(11.7,5.6)
NetCN1_B5: CN1.B5 R7.2 | length 10.8
  Top Layer 1 w0.254: R7.2 v1(8.2,10.2) ; CN1.B5 14.751,5.749 v1(14.8,5.7)
  Bottom Layer 1 w0.254: v1(8.2,10.2) 12.7,5.7 v1(14.8,5.7)
NetCN3_3: CN3.3 U1.34 | length 12.2
  Top Layer 1 w0.203: v1(25.715,29.87) 25.896,29.87 U1.34 ; v1(33.9,30.3) 35.065,30.3 CN3.3
  Bottom Layer 1 w0.203: v1(25.715,29.87) 25.849,29.87 26.031,30.052 26.052,30.052 27.8,31.8 31.6,31.8 33.1,30.3 v1(33.9,30.3)
NetCN3_5: CN3.5 U1.37 | length 12.6
  Top Layer 1 w0.203: U1.37 24.889,30.5 v1(24.9,30.5) ; v1(33.9,31.5) 35.065,31.5 CN3.5
  Bottom Layer 1 w0.203: v1(24.9,30.5) 25.8,30.5 27.5,32.2 32,32.2 32.7,31.5 v1(33.9,31.5)
NetD1_1: D1.1 U4.5 | length 1.6
  Top Layer 1 w0.152: D1.1 7.287,23.313 7.508,23.313
  Top Layer 1 w1.016: 7.508,23.313 U4.5@8.8,23.313
NetJP2_2: JP2.2 U1.7 | length 10.2
  Top Layer 1 w0.254: U1.7 23.2,24.346 23.2,24.7 v1(22.3,25.6)
  Bottom Layer 1 w0.254: JP2.2 21.7,26.2 v1(22.3,25.6)
NetJP3_2: JP3.2 U1.44 | length 13.9
  Top Layer 1 w0.254: U1.44 22.439,28 v1(22.5,28)
  Bottom Layer 1 w0.254: JP3.2 12.9,30.7 13.5,31.3 19.2,31.3 v1(22.5,28)
NetL1_1: L1.1 L2.2 U2.13 | length 4.6
  Top Layer 1 w0.337: U2.13 41.3,20.5 41.65,20.85 L2.2 L1.1
NetL2_1: L2.1 L3.2 U2.12 | length 5.1
  Top Layer 1 w0.337: U2.12 41.3,20 41.917,19.383 42.667,19.383 L2.1 42.725,19.35 43.007,19.068 43.007,18.793 43.45,18.35 L3.2
NetLD1_1: LD1.1 R3.1 | length 2.5
  Top Layer 1 w0.635: LD1.1 R3.1
NetLD2_1: LD2.1 R4.1 | length 3
  Top Layer 1 w0.635: LD2.1 R4.1
NetR1_1: R1.1 U2.16 | length 2.4
  Top Layer 1 w0.254: U2.16 39.153,22.453 39.153,23.053 39.9,23.8 R1.1
NetR5_2: R5.2 U3.9 | length 6.6
  Top Layer 1 w0.254: U3.9 15.146,11.5 16.9,11.5 17.5,12.1 17.5,13.2 18,13.7 18.75,13.7 R5.2@18.8,13.65
NetR8_1: R8.1 R9.2 U3.8 | length 7
  Top Layer 1 w0.254: U3.8 15.239,10.7 R8.1 R9.2
SCK: U1.15 U2.3 | length 11.1
  Top Layer 1 w0.254: U1.15 27.991,21.034 27.991,21.031 28.159,20.863 28.159,20.532 v1(28.245,20.447) ; v1(33.7,21.151) 33.785,21.066 33.785,20.772 34.057,20.5 U2.3
  Bottom Layer 1 w0.254: v1(28.245,20.447) 32.547,20.447 33.213,21.113 33.661,21.113 v1(33.7,21.151)
UART_RXD: U1.31 U3.21 | length 27
  Top Layer 1 w0.203: v1(10.9,16.8) 10.987,16.713 10.987,16.367 U3.21 ; v1(26.687,28.913) 26.688,28.914 27.061,28.914 U1.31
  Bottom Layer 1 w0.203: v1(10.9,16.8) 10.9,17.747 12.011,18.857 12.7,18.857 12.802,18.857 ccw(c12.802,19.06) 13.005,19.06 13.005,19.123 cw(c13.156,19.123) 13.308,19.123 13.308,18.962 ccw(c13.46,18.962) 13.611,18.962 13.611,19.123 cw(c13.763,19.123) 13.914,19.123 13.914,18.962 ccw(c14.066,18.962) 14.218,18.962 14.218,19.074 cw(c14.369,19.074) 14.521,19.074 14.521,18.962 ccw(c14.672,18.962) 14.824,18.962 14.824,19.06 cw(c14.976,19.06) 15.127,19.06 ccw(c15.33,19.06) 15.33,18.857 16.2,18.857 16.911,18.857 26.777,28.723 26.777,28.823 v1(26.687,28.913)
UART_TXD: U1.30 U3.20 | length 26.9
  Top Layer 1 w0.203: v1(11.7,17.3) 11.7,16.361 U3.20 ; v1(27.29,28.31) 27.29,28.436 U1.30
  Bottom Layer 1 w0.203: v1(11.7,17.3) 11.7,17.9 12.011,18.211 12.2,18.4 12.436,18.4 cw(c12.436,18.185) 12.651,18.185 12.651,17.925 ccw(c12.866,17.925) 13.081,17.925 13.081,18.19 cw(c13.296,18.19) 13.511,18.19 13.511,17.925 ccw(c13.726,17.925) 13.941,17.925 13.941,18.19 cw(c14.157,18.19) 14.372,18.19 14.372,17.993 ccw(c14.587,17.993) 14.802,17.993 14.802,18.19 cw(c15.017,18.19) 15.232,18.19 15.232,18.185 ccw(c15.447,18.185) 15.662,18.185 cw(c15.877,18.185) 15.877,18.4 17.1,18.4 17.207,18.507 27.1,28.4 27.2,28.4 v1(27.29,28.31)
USBD_N: CN1.A7 CN1.B7 U3.4 | length 11.6
  Top Layer 1 w0.203: U3.4 11.729,12.444 11.468,12.183 11.434,12.183 11.001,11.75 11.001,11.264 11.001,11.101 11.019,11.084 11.479,10.624 ccw(c11.623,10.768) 11.766,10.624 11.857,10.715 cw(c11.964,10.607) 12.071,10.715 cw(c11.964,10.607) 12.071,10.5 11.944,10.373 ccw(c12.051,10.266) 11.944,10.159 ccw(c12.051,10.266) 12.159,10.159 12.3,10.3 cw(c12.407,10.193) 12.514,10.3 cw(c12.407,10.193) 12.514,10.086 12.373,9.944 ccw(c12.48,9.837) 12.373,9.73 ccw(c12.48,9.837) 12.587,9.73 12.729,9.871 cw(c12.836,9.764) 12.943,9.871 cw(c12.836,9.764) 12.943,9.657 12.838,9.552 ccw(c12.982,9.408) 12.838,9.265 13.053,9.05 13.125,8.978 13.25,8.853 CN1.A7 13.202,6.922 13.202,6.187 13.005,5.991 12.495,5.991 12.298,6.187 12.298,6.922 CN1.B7
USBD_P: CN1.A6 CN1.B6 U3.3 | length 8.6
  Top Layer 1 w0.203: U3.3 11.444,12.729 11.183,12.468 11.183,12.434 10.646,11.897 10.646,10.954 10.75,10.85 12.1,9.5 12.574,9.026 v1(12.574,8.204) ; v1@12.669,8.173 12.669,7.975 12.702,7.942 CN1.A6@12.702,7.689 ; CN1.A6 CN1.A6@12.798,7.018 ; CN1.B6 13.783,7.003 v1@13.783,7.933
  Bottom Layer 1 w0.203: v1(12.574,8.204) v1(13.919,8.204)
XTGND: C1.2 C2.2 JP?.1 X1.2 X1.4
  other v1: 40.7,13.4 37.3,15.5 36.3,16.3
pads on no net: CN1. CN1.A8 CN1.B8 H1.1 H2.1 H3.1 H4.1 U1.2 U1.3 U1.4 U1.5 U1.6 U1.10 U1.13 U1.19 U1.20 U1.21 U1.22 U1.25 U1.26 U1.27 U1.28 U1.29 U1.32 U1.33 U1.38 U1.39 U1.40 U1.41 U1.42 U1.43 U1.45 U1.46 U2.6 U3.1 U3.10 U3.11 U3.12 U3.13 U3.14 U3.15 U3.16 U3.17 U3.18 U3.19 U3.22 U3.23 U3.24 U4.4
copper on no net:
  other v1: 4,1.682 46,1.682 2.319,2.282 5.681,2.282 44.319,2.282 47.681,2.282 1.719,3.963 6.281,3.963 43.719,3.963 48.281,3.963 2.319,5.644 5.681,5.644 44.319,5.644 47.681,5.644 4,6.244 46,6.244 4,27.682 46,27.682 2.319,28.282 5.681,28.282 44.319,28.282 47.681,28.282 1.719,29.963 6.281,29.963 43.719,29.963 48.281,29.963 2.319,31.644 5.681,31.644 44.319,31.644 47.681,31.644 4,32.244 46,32.244

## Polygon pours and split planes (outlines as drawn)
GND on Top Layer 1 "GND" (solid, remove dead copper, pour order 20): 46,0 ccw(c46,4) 50,4 50,7.3 41.5,7.3 41.5,11.5 35.2,11.5 35.2,22.9 34.2,23.9 34.2,27.1 50,27.1 50,30 ccw(c46,30) 46,34 4,34 ccw(c4,30) 0,30 0,4 ccw(c4,4) 4,0
3V3P on Top Layer 1 "3v3P" (solid, remove dead copper, pour order 16): 11.7,11.9 13.7,9.9 13.7,9.3 14.1,8.9 17.2,8.9 18.2,7.9 18.2,6.3 19.3,6.3 19.3,9.7 14.5,9.7 12.9,11.3 12.9,12.1 12.4,12.6
+5 on Top Layer 1 "5V" (solid, remove dead copper, pour order 14): 17.3,16.2 17.3,14.6 19.3,14.6 19.3,18.5 16.4,21.4 10.7,21.4 10.7,20.2 15.7,20.2 17.3,18.6
3V3 on Top Layer 1 "3v3" (solid, remove dead copper, pour order 12): 40.8,21.4 40.8,22.9 39.7,22.9 39.7,21.4
3V3 on Top Layer 1 "3v3" (solid, remove dead copper, pour order 13): 37.8,17.7 37.2,17.1 35.9,17.1 35.9,17.9 37.4,17.9 37.5,18 37.5,19 37.8,19
3V3 on Top Layer 1 "3v3" (solid, remove dead copper, pour order 11): 23.5,23 22.3,21.8 22.3,21.3 21,20 20.2,20.8 21.6,22.2 22.3,22.2 23.3,23.2
3V3 on Top Layer 1 "3v3" (solid, remove dead copper, pour order 10): 30.3,26.1 31,26.8 31.6,26.2 31,25.6 31,25.4 32.4,24 31.55,23.15 31.8,22.9 30.3,24.4 30.3,24.8 29.3,25.8 29.3,25.9 29.5,26.1
3V3 on Top Layer 1 "3v3" (solid, remove dead copper, pour order 4): 25.4,31 26.5,32.1 26.5,32.7 27.4,33.6 29.2,33.6 29.2,32.7 28,32.7 27.3,32 26.8,32 25.6,30.8
3V3 on Top Layer 1 "3v3" (solid, remove dead copper, pour order 0): 20.5,26.8 19.4,27.9 18.9,27.9 17,29.8 17.9,30.7 19.7,28.9 19.7,28.2 20.8,27.1
XTGND on Top Layer 1 "XTGND" (solid, remove dead copper, pour order 18): 42.2,12.5 41.5,11.8 35.5,11.8 35.5,16.8 41.1,16.8 42.2,15.7
AGND on Top Layer 1 "AGND" (solid, remove dead copper, pour order 17): 50,7.6 41.8,7.6 41.8,11.8 42.4,12.4 42.4,15.8 41.1,17.1 35.5,17.1 35.5,23 34.4,24.1 34.4,26.8 50,26.8
GND on Inner1 "GND1" (solid, remove dead copper, pour order 9): 46,0 ccw(c46,4) 50,4 50,7.3 41.5,7.3 41.5,11.5 35.2,11.5 35.2,22.9 34.1,24 34.1,27.249 50,27.249 50,30 ccw(c46,30) 46,34 4.008,34 ccw(c4,30) 0,30 0,4 ccw(c4,4) 4,0
XTGND on Inner1 "XTGND" (solid, remove dead copper, pour order 5): 42.2,12.5 41.5,11.8 35.5,11.8 35.5,16.8 41.1,16.8 42.2,15.7
AGND on Inner1 "AGND" (solid, remove dead copper, pour order 1): 50,7.6 41.8,7.6 41.8,11.8 42.4,12.4 42.4,15.8 41.1,17.1 35.5,17.1 35.5,23 34.4,24.1 34.4,26.8 50,26.8
+5 on Inner2 "5V" (solid, remove dead copper, pour order 19): 17.3,15.8 18.1,15.8 18.1,13.8 19.2,12.7 21.9,12.7 21.9,11.7 17.1,11.7 15.8,10.4 15.8,7.9 15.088,7.9 15.088,9.412 13.6,10.9 17.3,14.6
3V3 on Inner2 "3v3" (solid, remove dead copper, pour order 2): 30.683,18.313 30.886,18.11 30.912,18.1 36.8,18.1 36.848,18.052 36.848,17.1 28.7,17.1 28.2,16.6 19.2,16.6 16,19.8 12.1,19.8 7.6,15.3 3,15.3 3,21.8 9.2,28 9.2,32.4 10.4,33.6 29.2,33.6 31.9,30.9 31.9,25.7 29.7,25.7 29.7,30 28.3,31.4 18.9,31.4 18.6,31.1 18.6,23.7 21.6,20.7 20.7,19.8 17.3,23.2 17.3,31 16.9,31.4 12,31.4 11.4,30.8 11.4,26.9 5,20.5 5,17.5 5.2,17.3 7.6,17.3 11.2,20.9 16.6,20.9 19.8,17.7 27,17.7 34.5,25.2 39.8,25.2 40.8,24.2 40.8,21.8 39.6,21.8 39.6,23.1 38.9,23.8 35.4,23.8 30.683,19.083
XTGND on Inner2 "XTGND" (solid, remove dead copper, pour order 15): 35.5,16.8 35.5,12.9 42.2,12.9 42.2,15.7 41.1,16.8
AGND on Inner2 "AGND" (solid, remove dead copper, pour order 6): 50,7.6 41.8,7.6 41.8,11.8 42.4,12.4 42.4,15.8 41.1,17.1 35.5,17.1 35.5,23 34.4,24.1 34.4,26.8 50,26.8
GND on Bottom Layer 1 "GND" (solid, remove dead copper, pour order 8): 46,0 ccw(c46,4) 50,4 50,7.3 41.5,7.3 41.5,11.5 35.2,11.5 35.2,22.9 34.2,23.9 34.2,27.249 50,27.249 50,30 ccw(c46,30) 46,34 4,34 ccw(c4,30) 0,30 0,4 ccw(c4,4) 4,0
XTGND on Bottom Layer 1 "XTGND" (solid, remove dead copper, pour order 7): 42.2,12.5 41.5,11.8 35.5,11.8 35.5,16.8 41.1,16.8 42.2,15.7
AGND on Bottom Layer 1 "AGND" (solid, remove dead copper, pour order 3): 50,7.6 41.8,7.6 41.8,11.8 42.4,12.4 42.4,15.8 41.1,17.1 35.5,17.1 35.5,23 34.4,24.1 34.4,26.995 50,26.995

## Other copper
Top Layer 1:
  region net GND: 13.572,32.05 13.572,32.054 13.576,32.054 13.576,32.059 13.581,32.059 13.581,32.063 13.585,32.063 13.585,32.067 13.589,32.067 13.589,32.071 13.593,32.071 13.593,32.075 13.597,32.075 13.597,32.079 13.606,32.079 13.606,32.083 13.614,32.083 13.614,32.088 13.626,32.088 13.626,32.092 13.643,32.092 13.643,32.096 13.705,32.096 13.705,32.092 13.718,32.092 13.718,32.088 13.73,32.088 13.73,32.083 13.738,32.083 13.738,32.079 13.747,32.079 13.747,32.075 13.751,32.075 13.751,32.071 13.759,32.071 13.759,32.067 13.763,32.067 13.763,32.063 13.767,32.063 13.767,32.059 13.771,32.059 13.771,32.05 13.776,32.05 13.776,32.046 13.78,32.046 13.78,32.038 13.784,32.038 13.784,32.029 13.788,32.029 13.788,32.017 13.792,32.017 13.792,31.996 13.796,31.996 13.796,31.976 13.792,31.976 13.792,31.955 13.788,31.955 13.788,31.942 13.784,31.942 13.784,31.934 13.78,31.934 13.78,31.926 13.776,31.926 13.776,31.922 13.771,31.922 13.771,31.913 13.767,31.913 13.767,31.909 13.763,31.909 13.763,31.905 13.759,31.905 13.759,31.901 13.751,31.901 13.751,31.897 13.747,31.897 13.747,31.893 13.738,31.893 13.738,31.888 13.73,31.888 13.73,31.884 13.718,31.884 13.718,31.88 13.705,31.88 13.705,31.876 13.643,31.876 13.643,31.88 13.626,31.88 13.626,31.884 13.614,31.884 13.614,31.888 13.606,31.888 13.606,31.893 13.597,31.893 13.597,31.897 13.593,31.897 13.593,31.901 13.589,31.901 13.589,31.905 13.585,31.905 13.585,31.909 13.581,31.909 13.581,31.913 13.576,31.913 13.576,31.918 13.572,31.918 13.572,31.922 13.568,31.922 13.568,31.926 13.564,31.926 13.564,31.934 13.56,31.934 13.56,31.942 13.556,31.942 13.556,31.959 13.552,31.959 13.552,32.013 13.556,32.013 13.556,32.029 13.56,32.029 13.56,32.038 13.564,32.038 13.564,32.046 13.568,32.046 13.568,32.05
  region net GND: 431 vertices and 0 holes, not listed, extent 10.487,31.868 11.134,32.419
  region net GND: 303 vertices and 0 holes, not listed, extent 11.217,31.884 11.847,32.643
  region net GND: 251 vertices and 0 holes, not listed, extent 11.93,31.872 12.535,32.598
  region net GND: 471 vertices and 0 holes, not listed, extent 14.082,31.868 14.68,32.436
  region net GND: 561 vertices and 1 holes, not listed, extent 9.819,31.826 10.362,32.681
  region net GND: 312 vertices and 0 holes, not listed, extent 12.647,31.884 13.278,32.436
  region net GND: 343 vertices and 1 holes, not listed, extent 14.804,31.868 15.414,32.436
  region net GND: 297 vertices and 1 holes, not listed, extent 15.501,31.868 16.144,32.643
  region net GND: 1213 vertices and 1 holes, not listed, extent 8.989,31.2 17.006,33.34
Bottom Layer 1:
  region net GND: 1121 vertices and 0 holes, not listed, extent 35.772,1.606 41.425,6.923
  region net GND: 402 vertices and 0 holes, not listed, extent 32.153,2.425 33.468,3.72
  region net GND: 508 vertices and 0 holes, not listed, extent 30.51,3.939 32.313,5.882
  region net GND: 1113 vertices and 4 holes, not listed, extent 29.145,1.758 33.847,3.82
  region net GND: 160 vertices and 0 holes, not listed, extent 25.781,1.737 26.102,2.058
  region net GND: 5829 vertices and 9 holes, not listed, extent 22.123,0.867 27.862,6.696

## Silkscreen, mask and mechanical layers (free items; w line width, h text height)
Top Overlay:
  text "SWD/JTAG" at 33.865,27.115 h1.5
  text "HW v00 / '.Print_Date'" at 23.012,25.698 h1
  text "+  -" at 1.11,17.678 h3 r270
  text "e" at 23.881,15.315 h1.5
  text "SWITCH" at 24.763,15.31 h1.5
  text "\"JLCJLCJLCJLC\"" at 9.441,2.479 h1
Board:
  the board outline again, w0.127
